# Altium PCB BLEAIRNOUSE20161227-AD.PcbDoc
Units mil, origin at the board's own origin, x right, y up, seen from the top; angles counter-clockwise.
Board outline 1188.98 x 307.09 mil, 2 copper layers (Top, Bottom), stack 12.7 mil thick; 72 components, 42 nets, 224 pads, 2 vias.
Unrouted connection lines stored in the file: 131.
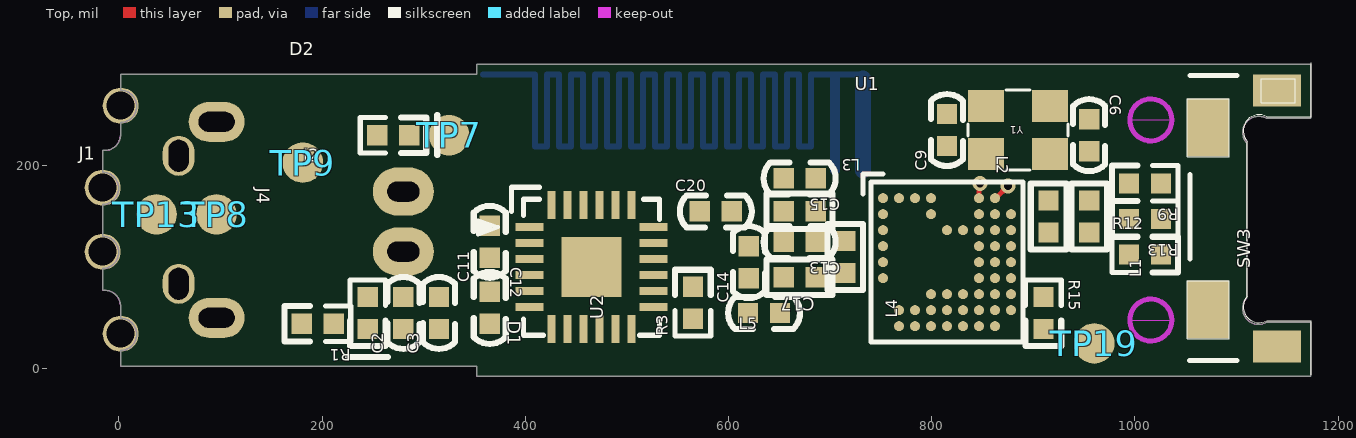
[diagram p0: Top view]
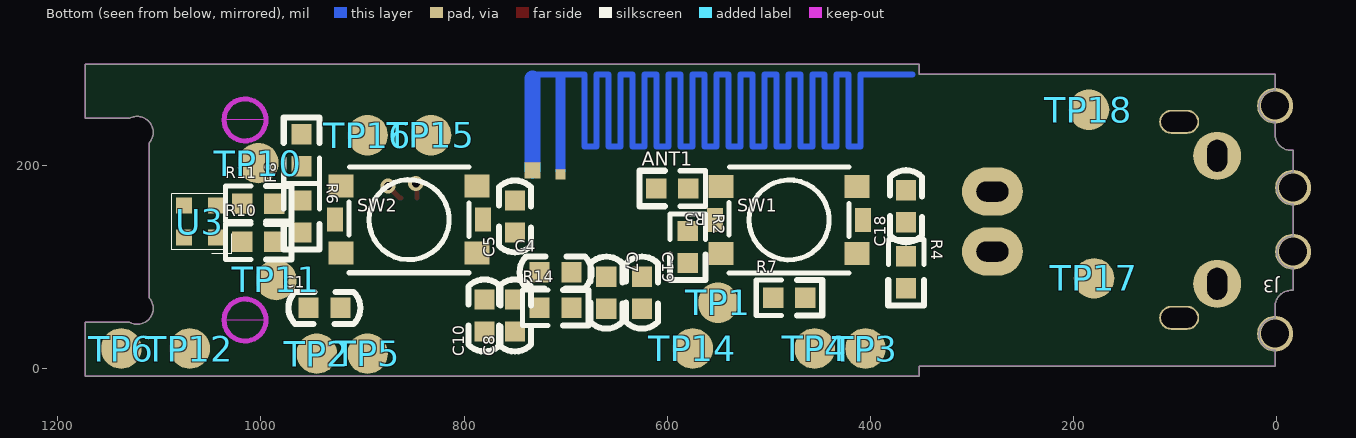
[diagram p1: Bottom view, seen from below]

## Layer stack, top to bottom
Solder Mask Top: solder mask 0.4, Solder Resist, Dk 3.5
Top: signal copper 1.35
Dielectric 1: dielectric 10, FR-4, Dk 4.3
Bottom: signal copper 1.35
Solder Mask Bottom: solder mask 0.4, Solder Resist, Dk 3.5

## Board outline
-14,215 ccw(c-14,230.75) 1.75,230.75 1.75,242.56 ccw(c1.75,258.31) 1.75,274.06 1.75,289.8 352.14,289.8 352.14,299.65 1173.01,299.65 1173.01,246.5 1129.45,246.5 1129.46,246.49 ccw(c1121.83,232.72) 1110.02,222.3 1110.02,69.9 1110.01,69.9 ccw(c1121.83,59.49) 1129.45,45.71 1173.01,45.71 1173.01,-7.44 352.14,-7.44 352.14,2.4 1.75,2.4 1.75,18.15 ccw(c1.75,33.9) 1.75,49.65 1.75,61.46 ccw(c-14,61.46) -14,77.2 -15.97,77.2 -15.97,98.86 ccw(c-15.97,114.61) -15.97,130.35 -15.97,161.85 ccw(c-15.97,177.6) -15.97,193.35 -15.97,215

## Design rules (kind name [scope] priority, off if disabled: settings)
Clearance "Clearance - Default - DEFAULT- SMD" [IsVia vs IsSMTPin] p1: gap=6
Clearance "Clearance - Default - DEFAULT - Via" [IsVia vs IsVia] p2: gap=6
Clearance "Clearance - Default - DEFAULT - Net" [All] p3: gap=6 except(10: Text-Text)
ComponentClearance "ComponentClearance - Default - DEFAULT" [All] p1: gap=6 collisioncheckmode=3 verticalgap=10 showdistances=FALSE
FanoutControl Fanout_Small [(CompPinCount < 5)] p3: bgadir=Out bgaviamode=Centered fanoutstyle=Auto fanoutdirection=OutThenIn viagrid=1 // Fanout_Small (Default Rule)
FanoutControl Fanout_SOIC [IsSOIC] p4: bgadir=Out bgaviamode=Centered fanoutstyle=Auto fanoutdirection=Alternating viagrid=1 // Fanout_SOIC (Default Rule)
HoleToHoleClearance "HoleToHoleClearance - Default - DEFAULT" [All] p1: gap=6 allowstackedmicrovias=TRUE
Length "Default Length" [All] p1: maxlimit=50000 minlimit=0
MaxMinImpedance "Default Impedance" [All] p1: minimum=50.00 maximum=150.0
ParallelSegment "Default Parallel Segment Adjasent" [All] p1: limit=1000 gap=200
ParallelSegment "Default Parallel Segment Same Layer" [All] p2: limit=1000 gap=200
PlaneConnect "Default PlaneConnect" [All] p1: planeconnectstyle=Relief reliefexpansion=20 reliefentries=0 reliefconductorwidth=15 reliefairgap=10
PolygonConnect "PolygonConnect - Default SMT" [IsSMTPin] p1: connectstyle=Relief reliefconductorwidth=10 reliefentries=4 polygonreliefangle="45 Angle" airgapwidth=10
PolygonConnect "PolygonConnect - Default Pad" [All] p2: connectstyle=Relief reliefconductorwidth=15 reliefentries=4 polygonreliefangle="45 Angle" airgapwidth=10
RoutingLayers "RoutingLayers - Default - DEFAULT" [All] p1: top layer_v5=TRUE bottom layer_v5=TRUE
RoutingPriority "RoutingPriority - Default - DEFAULT" [All] p1: routingpriority=3
RoutingTopology "Default Routing Topology" [All] p1: topology=Shortest
RoutingVias "RoutingVias - Default - DEFAULT" [All] p1: holewidth=8 width=15 viastyle="Through Hole" minholewidth=8 minwidth=15 maxholewidth=8 maxwidth=15
SMDToCorner "SMDToCorner - Default - DEFAULT" [All] p1: distance=60000
SolderMaskExpansion [All] p1: expansion=4
Width "Default Width" [All] p1: maxlimit=100 minlimit=5 preferedwidth=5
22 further rules are at their usual default settings.

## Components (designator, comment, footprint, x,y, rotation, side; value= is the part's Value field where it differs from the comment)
ANT1 "ANT_PIFA_2G4_UPDATED_0MM6" ANT_PIFA_2G4_UPDATED_0MM6 705,195 r180 bottom
C1 "C0402B" C0402B 937.5,60 r180 bottom
C2 "C0402B" C0402B 280,55 r90 top
C3 "C0402B" C0402B 315,55 r90 top
C4 "C0402B" C0402B 710,95 r180 bottom
C5 "C0402B" C0402B 750,150 r90 bottom
C6 "C0402B" C0402B 955,230 r270 top
C7 "C0402B" C0402B 660,75 r270 bottom
C8 "C0402B" C0402B 750,52.5 r90 bottom
C9 "C0402B" C0402B 815,235 r90 top
C10 "C0402B" C0402B 780,52.5 r90 bottom
C11 "C0402B" C0402B 365,125 r90 top
C12 "C0402B" C0402B 365,60 r270 top
C13 "C0402B" C0402B 670,125 r180 top
C14 "C0402B" C0402B 620,105 r90 top
C15 "C0402B" C0402B 670,187.5 r180 top
C17 "C0402B" C0402B 635,55 r180 top
C18 "C0402B" C0402B 365,160 r90 bottom
C19 "C0402B" C0402B 625,75 r270 bottom
C20 "C0402B" C0402B 587.5,155 r0 top
D1 "SOD723" SOD723 245,55 r270 top
D2 "SOD723" SOD723 270,230 r0 top
J1 "BAT+" BAT+ 58.8,146.7 r0 top
J2 "BAT-" BAT- 280,145 r0 top
J3 "BAT-JC" BAT-JC 96.2,146.65 r0 bottom
J4 "DIP4-2_0A" DIP4-2_0A -15.94,146.75 r270 top
L1 "L0402B" L0402B 955,150 r90 top
L2 "L0402B" L0402B 915,150 r270 top
L3 "L0402B" L0402B 670,155 r180 top
L4 "L0402B" L0402B 715,110 r90 top
L5 "L0402B" L0402B 670,90 r0 top
R1 "R0402" R0402 195.67,44.38 r180 top
R2 "R0402" R0402 580,120 r270 bottom
R3 "R0402" R0402 565,65 r90 top
R4 "R0402" R0402 365,95 r270 bottom
R5 "R0402" R0402 595,177.5 r0 bottom
R6 "R0402" R0402 960,150 r270 bottom
R7 "R0402" R0402 480,70 r180 bottom
R8 "R0402" R0402 960,215 r90 bottom
R9 "R0402" R0402 1010,182.5 r180 top
R10 "R0402" R0402 1002.5,125 r180 bottom
R11 "R0402" R0402 1002.5,162.5 r180 bottom
R12 "R0402" R0402 1010,112.5 r0 top
R13 "R0402" R0402 1010,147.5 r180 top
R14 "R0402" R0402 710,60 r180 bottom
R15 "R0402" R0402 910,55 r270 top
SW1 "SW-3_5X2_7-SMD" SW-3_5X2_7-SMD 480.12,146.57 r180 bottom
SW2 "SW-3_5X2_7-SMD" SW-3_5X2_7-SMD 854.13,146.77 r180 bottom
SW3 "EVQP4" EVQP4 1072.05,147.95 r90 top
TP1 "TP-1MM" TP-1MM 550,65 r180 bottom
TP2 "TP-1MM" TP-1MM 945,15 r180 bottom
TP3 "TP-1MM" TP-1MM 405,20 r180 bottom
TP4 "TP-1MM" TP-1MM 455,20 r180 bottom
TP5 "TP-1MM" TP-1MM 895,15 r180 bottom
TP6 "TP-1MM" TP-1MM 1137.5,20 r180 bottom
TP7 "TP-1MM" TP-1MM 325,230 r0 top
TP8 "TP-1MM" TP-1MM 96,152 r0 top
TP9 "TP-1MM" TP-1MM 181,203 r0 top
TP10 "TP-1MM" TP-1MM 1002.5,202.5 r180 bottom
TP11 "TP-1MM" TP-1MM 985,87.5 r180 bottom
TP12 "TP-1MM" TP-1MM 1070,20 r180 bottom
TP13 "TP-1MM" TP-1MM 37,152 r0 top
TP14 "TP-1MM" TP-1MM 575,20 r180 bottom
TP15 "TP-1MM" TP-1MM 832.5,230 r180 bottom
TP16 "TP-1MM" TP-1MM 895,230 r180 bottom
TP17 "TP-1MM" TP-1MM 180,89 r180 bottom
TP18 "TP-1MM" TP-1MM 185,255 r180 bottom
TP19 "TP-1MM" TP-1MM 960,25 r0 top
U1 "NRF51822WLCSP" NRF51822WLCSP 815,105 r0 top
U2 "QFN24-3X3" QFN24-3X3 465,100 r90 top
U3 "LED_RGB_1MMX1MM" LED_RGB_1MMX1MM 1060,145 r180 bottom
Y1 "X2520" X2520 885,235 r180 top

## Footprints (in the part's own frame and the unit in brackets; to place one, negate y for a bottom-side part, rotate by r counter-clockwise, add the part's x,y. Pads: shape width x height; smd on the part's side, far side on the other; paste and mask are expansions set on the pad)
ANT_PIFA_2G4_UPDATED_0MM6 [mm]
  rrect0% 0.25x0.25 smd: 1(0,-0.1)
  rect 0.4x0.4 smd: 2(-0.7,0)
  Top lines w0.15: 8.8,2.4 7.8,2.4 7.5,2.4 7.5,0.6 7.2,0.6 7.2,2.4 6.9,2.4 6.9,0.6 6.6,0.6 6.6,2.4 6.3,2.4 6.3,0.6 6,0.6 6,2.4 5.7,2.4 5.7,0.6 5.4,0.6 5.4,2.4 5.1,2.4 5.1,0.6 4.8,0.6 4.8,2.4 4.5,2.4 4.5,0.6 4.2,0.6 4.2,2.4 3.9,2.4 3.9,0.6 3.6,0.6 3.6,2.4 3.3,2.4 3.3,0.6 3,0.6 3,2.4 2.7,2.4 2.7,0.6 2.4,0.6 2.4,2.4 2.1,2.4 2.1,0.6 1.8,0.6 1.8,2.4 1.5,2.4 1.5,0.6 1.2,0.6 1.2,2.4 0.9,2.4 0.9,0.6 0.6,0.6 0.6,2.4 0,2.4 ; 0,0 0,2.4 ; -0.7,2.4 0,2.4
  Top lines w0.25: 0,0 0,2.3
  Top lines w0.4: -0.7,0 -0.7,2.3
BAT+ [mm]
  oval 0.8x1 / inner oval 0.8x1 / far side rrect100% 1.2x1.2 hole 0.5 slot 0.8 at 90 deg: 1(0,1.6) 2(0,-1.6)
BAT- [mm]
  oval 1.524x1.2 hole 0.5 slot 0.8 at 0 deg: 1(0,0.75) 2(0,-0.75)
BAT-JC [mm]
  oval 1x0.6 / inner oval 1x0.6 / far side oval 1.4x1 hole 0.5 slot 0.9 at 0 deg: 1(0,2.45) 2(0,-2.45)
C0402B [mil]
  rect 20x20 smd: 1(-15.75,0) 2(15.75,0)
  silkscreen extent -35,-16 35,16
DIP4-2_0A [mm]
  round 0.9 hole 0.7: 1(2.85,0.45) 2(0.8,0) 3(-0.8,0) 4(-2.85,0.45)
EVQP4 [mm]
  rect 1.45x1.05 smd: 1(-2.275,0) 2(2.275,0)
  rect 0.8x1.2 smd: 3(-3.2,-1.725) 4(3.2,-1.725)
  silkscreen extent -3.91,-2.58 3.9,0.53
L0402B [mil]
  rect 20x20 smd: 1(-15.75,0) 2(15.75,0)
  silkscreen extent -32,-18 32,18
LED_RGB_1MMX1MM [mm]
  rect 0.4x0.4 smd: 1(0.4,-0.4) 2(0.4,0.4) 3(-0.4,0.4) 4(-0.4,-0.4)
  silkscreen extent -0.7,-0.8 0.8,0.7
NRF51822WLCSP [mm]
  round 0.25 smd: A1(-1.6,1.6) A2(-1.2,1.6) A3(-0.8,1.6) A4(-0.4,1.6) A7(0.8,1.6) A8(1.2,1.6) B1(-1.6,1.2) B4(-0.4,1.2) B7(0.8,1.2) B8(1.2,1.2) B9(1.6,1.2) C1(-1.6,0.8) C5(0,0.8) C6(0.4,0.8) C7(0.8,0.8) C8(1.2,0.8) C9(1.6,0.8) D1(-1.6,0.4) D7(0.8,0.4) D8(1.2,0.4) D9(1.6,0.4) E1(-1.6,0) E7(0.8,0) E8(1.2,0) E9(1.6,0) F1(-1.6,-0.4) F7(0.8,-0.4) F8(1.2,-0.4) F9(1.6,-0.4) G4(-0.4,-0.8) G5(0,-0.8) G6(0.4,-0.8) G7(0.8,-0.8) G8(1.2,-0.8) G9(1.6,-0.8) H2(-1.2,-1.2) H3(-0.8,-1.2) H4(-0.4,-1.2) H5(0,-1.2) H6(0.4,-1.2) H7(0.8,-1.2) H8(1.2,-1.2) H9(1.6,-1.2) J2(-1.2,-1.6) J3(-0.8,-1.6) J4(-0.4,-1.6) J5(0,-1.6) J6(0.4,-1.6) J7(0.8,-1.6) J8(1.2,-1.6)
  round 0 all layers, no hole: A5(0,0) A6(0,0) B5(0,0) B6(0,0) E2(0,0) E3(0,0) F2(0,0) F3(0,0) G1(0,0) G2(0,0) G3(0,0) H1(0,0)
  silkscreen extent -2.1,-2 1.9,2.2
QFN24-3X3 [mm]
  rect 0.2x0.7 smd: 1(1,1.55) 2(0.6,1.55) 3(0.2,1.55) 4(-0.2,1.55) 5(-0.6,1.55) 6(-1,1.55) 13(-1,-1.55) 14(-0.6,-1.55) 15(-0.2,-1.55) 16(0.2,-1.55) 17(0.6,-1.55) 18(1,-1.55)
  rect 0.7x0.2 smd: 7(-1.55,1) 8(-1.55,0.6) 9(-1.55,0.2) 10(-1.55,-0.2) 11(-1.55,-0.6) 12(-1.55,-1) 19(1.55,-1) 20(1.55,-0.6) 21(1.55,-0.2) 22(1.55,0.2) 23(1.55,0.6) 24(1.55,1)
  rect 1.5x1.5 smd: 25(0,0)
  silkscreen extent -1.7,-1.7 2,2.83
R0402 [mil]
  rect 20x20 smd: 1(-15.75,0) 2(15.75,0)
  silkscreen extent -32,-18 32,18
SOD723 [mil]
  rect 20x20 smd: 1(-15.75,0) 2(15.75,0)
  silkscreen extent -32,-20 43,20
SW-3_5X2_7-SMD [mm]
  rect 0.625x0.575 smd: 1(-1.7,0.837) 2(-1.7,-0.837) 3(1.7,0.837) 4(1.7,-0.837)
  rect 0.4x0.6 smd: 5(1.85,0) 6(-1.85,0)
  silkscreen extent -1.51,-1.33 1.5,1.32
TP-1MM [mil]
  round 40 smd: 1(0,0)
X2520 [mm]
  rect 0.9x0.8 smd: 1(-0.8,-0.6) 2(0.8,-0.6) 3(0.8,0.6) 4(-0.8,0.6)
  silkscreen extent -1.25,-1 1.25,1

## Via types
v1: diameter 15, hole 8, Top to Bottom, 2 vias

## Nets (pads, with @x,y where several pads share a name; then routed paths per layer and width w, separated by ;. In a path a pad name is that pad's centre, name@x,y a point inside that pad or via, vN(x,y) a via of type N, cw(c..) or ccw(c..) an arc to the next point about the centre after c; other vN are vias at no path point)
ANT1: L4.1 L5.2 U1.D1
ANT2: C13.1 L4.2 U1.C1
AREF0: R12.1 R13.2 U1.C9
AVDD: C1.1 L1.2 U1.A1
B_LED: R11.2 TP10.1 U1.J4
G_LED: R10.2 TP11.1 U1.H4
GND: C1.2 C2.2 C3.2 C4.2 C5.2 C6.2 C7.2 C8.2 C9.2 C10.2 C11.2 C12.2 C14.1 C15.2 C17.2 C18.2 C19.2 C20.2 D1.1 J2.1 J2.2 R1.1 R7.2 R8.2 R13.1 R14.2 TP17.1 U1.B1 U1.B4 U1.C8 U1.D7 U1.G6 U1.G9 U1.H3 U2.1 U2.11 U2.18 U2.25 Y1.2 Y1.4
I2C_SCL: R3.2 TP1.1 U1.E9 U2.23
I2C_SDA: R2.2 TP2.1 U1.F8 U2.24
INT_MPU6050: TP4.1 U1.F9 U2.12
KEY0: R5.2 TP5.1 U1.J8
KEY1: R6.2 TP6.1 U1.H6
KEY2: R15.2 TP19.1 U1.J5
N756550: C11.1 R4.2 U2.8
N756642: C12.1 U2.10
N760581: R5.1 R7.1 SW1.1
N760880: R6.1 R8.1 SW2.1
N770152: TP3.1 U2.9
N772398: C4.1 U1.F1
N772402: C5.1 U1.A4
N772486: TP16.1 U1.A8 | length 17.7
  Top w5: U1.A8 862.99,167.99 v1(875,180)
N774070: L1.1 L2.2
N774429: L2.1 U1.B9
N780506: D2.1 J3.1 J3.2
N781791: R9.1 U3.4
N786255: ANT1.1 C15.1 L3.1
N786271: C13.2 C14.2 L3.2
N793028: R10.1 U3.3
N793032: R11.1 U3.2
N795092: TP15.1 U1.A7 | length 14.9
  Top w5: U1.A7 846.5,181.5 v1(847.5,182.5)
N796039: C20.1 U2.20
N798202: R14.1 R15.1 SW3.1
P05: J4.1 TP14.1 U1.H9
P06: J4.2 TP13.1 U1.G8
R_LED: R9.2 TP12.1 U1.H5
SWDCLK: J4.4 R1.2 TP9.1 U1.H2
SWDIO: J4.3 TP8.1 U1.J2
VBAT_DECT: D2.2 TP7.1 U1.D9
VDD_NRF: C2.1 C3.1 C7.1 C8.1 C10.1 C18.1 C19.1 D1.2 J1.1 J1.2 R2.1 R3.1 R4.1 R12.2 SW1.2 SW2.2 SW3.2 TP18.1 U1.B8 U1.H8 U2.13 U3.1
VDD_PA: C17.1 L5.1 U1.E1
XC1: C9.1 U1.A2 Y1.3
XC2: C6.1 U1.A3 Y1.1
pads on no net: ANT1.2 SW1.3 SW1.4 SW1.5 SW1.6 SW2.3 SW2.4 SW2.5 SW2.6 SW3.3 SW3.4 U1.A5 U1.A6 U1.B5 U1.B6 U1.B7 U1.C5 U1.C6 U1.C7 U1.D8 U1.E2 U1.E3 U1.E7 U1.E8 U1.F2 U1.F3 U1.F7 U1.G1 U1.G2 U1.G3 U1.G4 U1.G5 U1.G7 U1.H1 U1.H7 U1.J3 U1.J6 U1.J7 U2.2 U2.3 U2.4 U2.5 U2.6 U2.7 U2.14 U2.15 U2.16 U2.17 U2.19 U2.21 U2.22

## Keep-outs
Keep-Out Layer:
  circle w5: c1015.67,245 r20.67
  circle w5: c1015.67,48 r20.67
  lines w1: 995,48 1036.34,48 ; 995,245 1036.34,245 ; -15.97,77.2 -14,77.2 cw(c-14,61.46) 1.75,61.46 1.75,49.65 cw(c1.75,33.9) 1.75,18.15 1.75,2.4 352.14,2.4 352.14,-7.44 1173.01,-7.44 1173.01,45.71 1129.45,45.71 cw(c1121.83,59.49) 1110.01,69.9 1110.02,222.3 cw(c1121.83,232.72) 1129.46,246.49 1173.01,246.5 1173.01,299.65 352.14,299.65 352.14,289.8 1.75,289.8 1.75,274.06 cw(c1.75,258.31) 1.75,242.56 1.75,230.75 cw(c-14,230.75) -14,215 -15.97,215 -15.97,193.35 cw(c-15.97,177.6) -15.97,161.85 -15.97,130.35 cw(c-15.97,114.61) -15.97,98.86 -15.97,77.2

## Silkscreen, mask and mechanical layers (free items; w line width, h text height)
Assembly Drawing Top:
  drawing of 3792 lines, arcs and shapes, not listed
Assembly Drawing Bottom:
  drawing of 10724 lines, arcs and shapes, not listed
